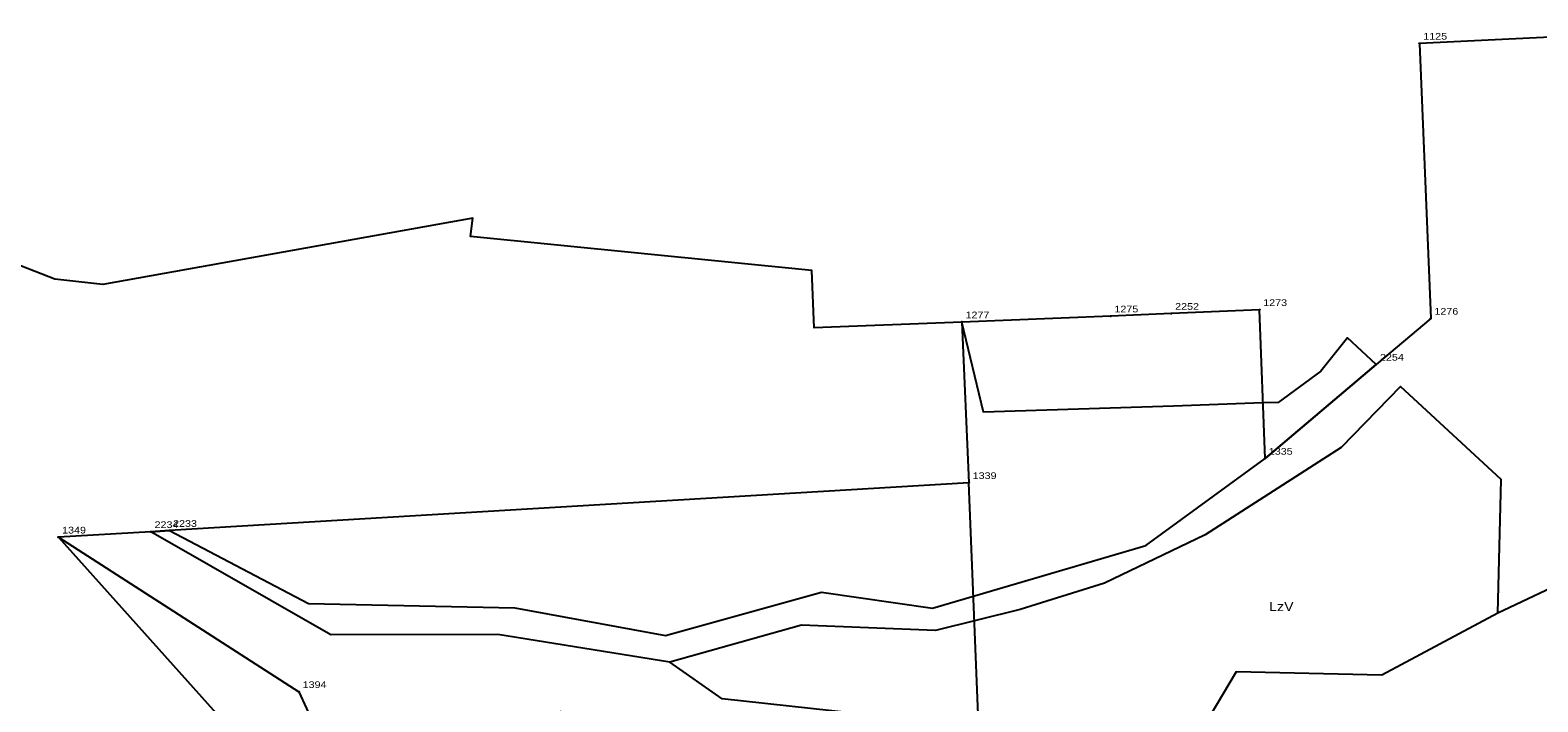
# Model space of a CAD drawing. Extents: x 4640203 to 4641683, y 5358965 to 5360242.
# Drawn here: x 4640818.7 to 4641021.5, y 5360097.3 to 5360187.6 of the extents above; entities that cross this region are included whole.
import ezdxf

# ---------------------------------------------------------------- set-up
doc = ezdxf.new("R2010")
doc.units = 0
doc.header["$LTSCALE"] = 0.36
for name, color, linetype, lineweight in [('25', 7, 'Continuous', 25), ('27', 7, 'Continuous', 25), ('8', 7, 'Continuous', 25)]:
    doc.layers.add(name, color=color, linetype=linetype, lineweight=lineweight)
doc.layers.add('26', color=7, linetype='Continuous')

msp = doc.modelspace()

# ---------------------------------------------------------------- linework, layer by layer
at = {"layer": '25'}
msp.add_line((4640944.04, 5360148.37), (4640945, 5360126.76), dxfattribs=at)
for points in [[(4641136.45, 5360120.8), (4641136.4, 5360131.27), (4641125.62, 5360130.26), (4641104.01, 5360128.24), (4641085.07, 5360126.47), (4641066.3, 5360124.77), (4641045.26, 5360122.78), (4641044.03, 5360152.74), (4641042.58, 5360187.61), (4641039.28, 5360187.45), (4641028.77, 5360186.95), (4641005.62, 5360185.84), (4641007.12, 5360148.86), (4640999.8, 5360142.67), (4640984.84, 5360130.03), (4640984.09, 5360150.02), (4640972.24, 5360149.51), (4640964.07, 5360149.16), (4640944.04, 5360148.37)], [(4640948.43, 5360041.06), (4640945, 5360126.76), (4640837.42, 5360120.32), (4640834.93, 5360120.17), (4640822.49, 5360119.43)], [(4640822.49, 5360119.43), (4640854.85, 5360098.66), (4640861.04, 5360085.2), (4640862.68, 5360079.91), (4640867.92, 5360046.79), (4640868.84, 5360040.95), (4640878.93, 5360042.62), (4640891.73, 5360042.91), (4640903.68, 5360042.83), (4640906.93, 5360042.81), (4640924.19, 5360042.08), (4640932.05, 5360041.75), (4640946.29, 5360041.15)]]:
    msp.add_lwpolyline(points, dxfattribs=at)
at = {"layer": '27'}
for points in [[(4640834.93, 5360120.17), (4640837.42, 5360120.32), (4640856.12, 5360110.54), (4640883.88, 5360109.92), (4640904.19, 5360106.22), (4640925.17, 5360112.06), (4640940.1, 5360109.9), (4640968.8, 5360118.34), (4640984.84, 5360130.03), (4640999.8, 5360142.67), (4640995.93, 5360146.23), (4640992.34, 5360141.74), (4640986.6, 5360137.56), (4640984.56, 5360137.49), (4640972.51, 5360137.07), (4640946.96, 5360136.24), (4640944.04, 5360148.37), (4640924.16, 5360147.57), (4640923.86, 5360155.31), (4640877.95, 5360159.88), (4640878.26, 5360162.32), (4640828.45, 5360153.42), (4640822.01, 5360154.11), (4640798.52, 5360163.29)], [(4641016.16, 5360109.22), (4641016.61, 5360127.19), (4641003.05, 5360139.68), (4640995.1, 5360131.51), (4640976.8, 5360119.77), (4640963.22, 5360113.24), (4640951.89, 5360109.72), (4640940.51, 5360106.91), (4640922.48, 5360107.6), (4640904.74, 5360102.63)], [(4641030.67, 5360116.09), (4641016.16, 5360109.22), (4641000.54, 5360100.88), (4640980.96, 5360101.32), (4640974.02, 5360089.65), (4640953.61, 5360093.11), (4640911.8, 5360097.69), (4640904.74, 5360102.63), (4640881.63, 5360106.36), (4640859.14, 5360106.32), (4640834.93, 5360120.17), (4640822.49, 5360119.43)], [(4640822.49, 5360119.43), (4640852.21, 5360086.33), (4640833.84, 5360073.62), (4640862.68, 5360079.91), (4640868.93, 5360080.45), (4640884.1, 5360094.66), (4640890.03, 5360095.98), (4640917.84, 5360074.12), (4640983.91, 5360073.31), (4640989.6, 5360066.09), (4640998.04, 5360054.42), (4641003.79, 5360049.43), (4641013.49, 5360042.47)]]:
    msp.add_lwpolyline(points, dxfattribs=at)
at = {"layer": '8'}
for centre in [(4641005.62, 5360185.84), (4640984.09, 5360150.02), (4640944.04, 5360148.37), (4640964.07, 5360149.16), (4640972.24, 5360149.51), (4641007.12, 5360148.86), (4640999.8, 5360142.67), (4640984.84, 5360130.03), (4640945, 5360126.76), (4640822.49, 5360119.43), (4640834.93, 5360120.17), (4640837.42, 5360120.32), (4640854.85, 5360098.66)]:
    msp.add_circle(centre, 0.045, dxfattribs=at)

# ---------------------------------------------------------------- texts
at = {"layer": '26', "width": 1.15}
msp.add_text('LzV', height=1.25, dxfattribs=at).set_placement((4640985.37, 5360109.49))
at = {"layer": '8', "width": 1.2}
for s, p in [('1125', (4641006.12, 5360186.34)), ('1277', (4640944.54, 5360148.87)), ('1275', (4640964.57, 5360149.66)), ('2252', (4640972.74, 5360150.01)), ('1273', (4640984.59, 5360150.52)), ('1276', (4641007.62, 5360149.36)), ('2254', (4641000.3, 5360143.17)), ('1335', (4640985.34, 5360130.53)), ('1339', (4640945.5, 5360127.26)), ('2234', (4640835.43, 5360120.67)), ('2233', (4640837.92, 5360120.82)), ('1349', (4640822.99, 5360119.93)), ('1394', (4640855.35, 5360099.16))]:
    msp.add_text(s, height=0.9, dxfattribs=at).set_placement(p)

doc.saveas('drawing.dxf')
